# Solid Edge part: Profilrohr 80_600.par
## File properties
Username: ahadarics
Dokumentum tartalom típus: 0
Author: ahadarics
Last saved by: ahadarics
Revision: 88
Sűrűség: 0,000 kg/m^3
Pontosság: 0,990
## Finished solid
Body 1: solid body, 147 faces, 434 edges, 288 vertices.
  Faces by surface: cylinder 85, plane 62
  Edges by curve: line 264, circle 170
Bounding box of the edges (mm): 86.600 x 86.600 x 648.000, from (-43.3, -43.3, -611.5) to (43.3, 43.3, 36.5).
Cylindrical faces by radius (mm): R0.1 x8, R0.2 x30, R0.5 x22, R1 x8, R4.6 x4, R7 x4, R40 x1, R42.7 x8
Planar faces by outward normal: +x 6, +y 6, +z 1, -x 4, -y 4, -z 1, oblique 40
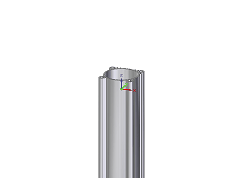
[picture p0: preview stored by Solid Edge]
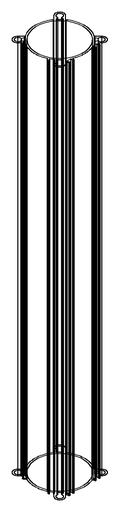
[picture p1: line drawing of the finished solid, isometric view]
